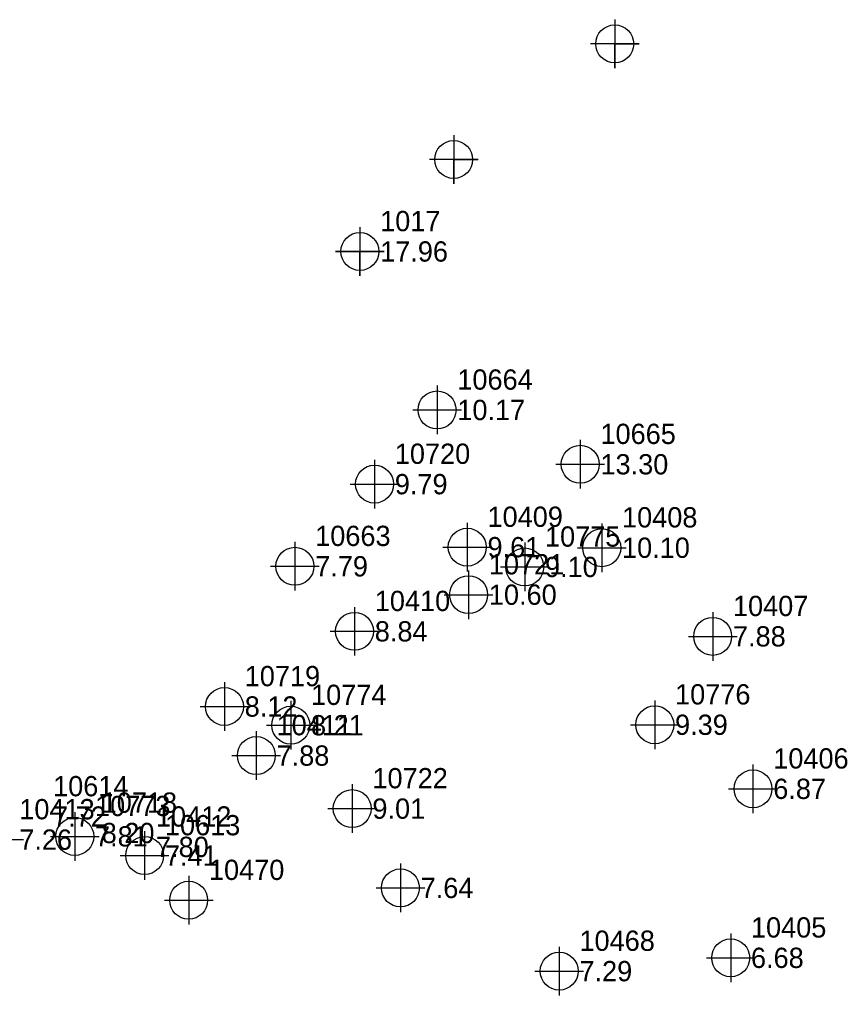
# Model space of a CAD drawing. Extents: x 2062781 to 2066835, y 358981 to 366501.
# Drawn here: x 2065189 to 2065291.1, y 361579.9 to 361700.3 of the extents above; entities that cross this region are included whole.
import ezdxf

# ---------------------------------------------------------------- set-up
doc = ezdxf.new("R2010")
doc.units = 0
for name, color, linetype in [('COGO Default Point Elevation', 7, 'Continuous'), ('COGO Default Point Number', 7, 'Continuous'), ('Exist DTM Breakline Underwater Cogo Elevation', 7, 'Continuous'), ('Exist DTM Breakline Underwater Cogo Number', 7, 'Continuous'), ('Exist DTM Breakline Underwater Cogo Point CELL', 7, 'Continuous'), ('Exist DTM Regular Point CELL', 7, 'Continuous'), ('Exist DTM Regular Point Underwater CELL', 7, 'Continuous')]:
    doc.layers.add(name, color=color, linetype=linetype)

msp = doc.modelspace()

# ---------------------------------------------------------------- linework, layer by layer
at = {"layer": 'Exist DTM Breakline Underwater Cogo Point CELL'}
msp.add_lwpolyline([(2065230.99, 361674.65), (2065230.99, 361668.65), (2065230.99, 361671.65), (2065233.99, 361671.65), (2065227.99, 361671.65)], dxfattribs=at)
msp.add_circle((2065230.99, 361671.65), 2.34, dxfattribs=at)
at = {"layer": 'Exist DTM Regular Point CELL'}
for points in [[(2065262.42, 361700.25), (2065262.42, 361694.25), (2065262.42, 361697.25), (2065265.42, 361697.25), (2065259.42, 361697.25)], [(2065242.56, 361685.99), (2065242.56, 361679.99), (2065242.56, 361682.99), (2065245.56, 361682.99), (2065239.56, 361682.99)]]:
    msp.add_lwpolyline(points, dxfattribs=at)
for centre in [(2065262.42, 361697.25), (2065242.56, 361682.99)]:
    msp.add_circle(centre, 2.34, dxfattribs=at)
at = {"layer": 'Exist DTM Regular Point Underwater CELL'}
for points in [[(2065230.99, 361674.65), (2065230.99, 361671.65)], [(2065227.99, 361671.65), (2065230.99, 361671.65)], [(2065230.99, 361671.65), (2065233.99, 361671.65)], [(2065230.99, 361671.65), (2065230.99, 361668.65)], [(2065240.51, 361655.11), (2065240.51, 361652.11)], [(2065237.51, 361652.11), (2065240.51, 361652.11)], [(2065240.51, 361652.11), (2065243.51, 361652.11)], [(2065240.51, 361652.11), (2065240.51, 361649.11)], [(2065258.16, 361648.41), (2065258.16, 361645.41)], [(2065232.8, 361645.96), (2065232.8, 361642.96)], [(2065255.16, 361645.41), (2065258.16, 361645.41)], [(2065258.16, 361645.41), (2065261.16, 361645.41)], [(2065258.16, 361645.41), (2065258.16, 361642.41)], [(2065229.8, 361642.96), (2065232.8, 361642.96)], [(2065232.8, 361642.96), (2065235.8, 361642.96)], [(2065232.8, 361642.96), (2065232.8, 361639.96)], [(2065244.23, 361638.19), (2065244.23, 361635.19)], [(2065260.82, 361638.12), (2065260.82, 361635.12)], [(2065222.98, 361635.83), (2065222.98, 361632.83)], [(2065251.32, 361635.75), (2065251.32, 361632.75)], [(2065241.23, 361635.19), (2065244.23, 361635.19)], [(2065244.23, 361635.19), (2065247.23, 361635.19)], [(2065244.23, 361635.19), (2065244.23, 361632.19)], [(2065257.82, 361635.12), (2065260.82, 361635.12)], [(2065260.82, 361635.12), (2065263.82, 361635.12)], [(2065260.82, 361635.12), (2065260.82, 361632.12)], [(2065219.98, 361632.83), (2065222.98, 361632.83)], [(2065222.98, 361632.83), (2065225.98, 361632.83)], [(2065222.98, 361632.83), (2065222.98, 361629.83)], [(2065244.4, 361632.33), (2065244.4, 361629.33)], [(2065248.32, 361632.75), (2065251.32, 361632.75)], [(2065251.32, 361632.75), (2065254.32, 361632.75)], [(2065251.32, 361632.75), (2065251.32, 361629.75)], [(2065241.4, 361629.33), (2065244.4, 361629.33)], [(2065244.4, 361629.33), (2065247.4, 361629.33)], [(2065244.4, 361629.33), (2065244.4, 361626.33)], [(2065230.33, 361627.81), (2065230.33, 361624.81)], [(2065274.5, 361627.19), (2065274.5, 361624.19)], [(2065227.33, 361624.81), (2065230.33, 361624.81)], [(2065230.33, 361624.81), (2065233.33, 361624.81)], [(2065230.33, 361624.81), (2065230.33, 361621.81)], [(2065271.5, 361624.19), (2065274.5, 361624.19)], [(2065274.5, 361624.19), (2065277.5, 361624.19)], [(2065274.5, 361624.19), (2065274.5, 361621.19)], [(2065214.29, 361618.54), (2065214.29, 361615.54)], [(2065267.36, 361616.29), (2065267.36, 361613.29)], [(2065211.29, 361615.54), (2065214.29, 361615.54)], [(2065214.29, 361615.54), (2065217.29, 361615.54)], [(2065214.29, 361615.54), (2065214.29, 361612.54)], [(2065222.47, 361616.23), (2065222.47, 361613.23)], [(2065219.47, 361613.23), (2065222.47, 361613.23)], [(2065222.47, 361613.23), (2065225.47, 361613.23)], [(2065222.47, 361613.23), (2065222.47, 361610.23)], [(2065264.36, 361613.29), (2065267.36, 361613.29)], [(2065267.36, 361613.29), (2065270.36, 361613.29)], [(2065267.36, 361613.29), (2065267.36, 361610.29)], [(2065218.22, 361612.49), (2065218.22, 361609.49)], [(2065215.22, 361609.49), (2065218.22, 361609.49)], [(2065218.22, 361609.49), (2065221.22, 361609.49)], [(2065218.22, 361609.49), (2065218.22, 361606.49)], [(2065279.47, 361608.39), (2065279.47, 361605.39)], [(2065230.04, 361605.95), (2065230.04, 361602.95)], [(2065276.47, 361605.39), (2065279.47, 361605.39)], [(2065279.47, 361605.39), (2065282.47, 361605.39)], [(2065279.47, 361605.39), (2065279.47, 361602.39)], [(2065195.83, 361602.52), (2065195.83, 361599.52)], [(2065227.04, 361602.95), (2065230.04, 361602.95)], [(2065230.04, 361602.95), (2065233.04, 361602.95)], [(2065230.04, 361602.95), (2065230.04, 361599.95)], [(2065192.83, 361599.52), (2065195.83, 361599.52)], [(2065195.83, 361599.52), (2065198.83, 361599.52)], [(2065195.83, 361599.52), (2065195.83, 361596.52)], [(2065204.45, 361600.16), (2065204.45, 361597.16)], [(2065186.49, 361599.13), (2065189.49, 361599.13)], [(2065201.45, 361597.16), (2065204.45, 361597.16)], [(2065204.45, 361597.16), (2065207.45, 361597.16)], [(2065204.45, 361597.16), (2065204.45, 361594.16)], [(2065235.99, 361596.17), (2065235.99, 361593.17)], [(2065209.88, 361594.65), (2065209.88, 361591.65)], [(2065232.99, 361593.17), (2065235.99, 361593.17)], [(2065235.99, 361593.17), (2065238.99, 361593.17)], [(2065235.99, 361593.17), (2065235.99, 361590.17)], [(2065206.88, 361591.65), (2065209.88, 361591.65)], [(2065209.88, 361591.65), (2065212.88, 361591.65)], [(2065209.88, 361591.65), (2065209.88, 361588.65)], [(2065276.72, 361587.55), (2065276.72, 361584.55)], [(2065255.57, 361585.91), (2065255.57, 361582.91)], [(2065273.72, 361584.55), (2065276.72, 361584.55)], [(2065276.72, 361584.55), (2065279.72, 361584.55)], [(2065276.72, 361584.55), (2065276.72, 361581.55)], [(2065252.57, 361582.91), (2065255.57, 361582.91)], [(2065255.57, 361582.91), (2065258.57, 361582.91)], [(2065255.57, 361582.91), (2065255.57, 361579.91)]]:
    msp.add_lwpolyline(points, dxfattribs=at)
for centre in [(2065230.99, 361671.65), (2065240.51, 361652.11), (2065258.16, 361645.41), (2065232.8, 361642.96), (2065244.23, 361635.19), (2065260.82, 361635.12), (2065222.98, 361632.83), (2065251.32, 361632.75), (2065244.4, 361629.33), (2065230.33, 361624.81), (2065274.5, 361624.19), (2065214.29, 361615.54), (2065222.47, 361613.23), (2065267.36, 361613.29), (2065218.22, 361609.49), (2065279.47, 361605.39), (2065230.04, 361602.95), (2065195.83, 361599.52), (2065204.45, 361597.16), (2065235.99, 361593.17), (2065209.88, 361591.65), (2065276.72, 361584.55), (2065255.57, 361582.91)]:
    msp.add_circle(centre, 2.34, dxfattribs=at)

# ---------------------------------------------------------------- texts
at = {"layer": 'COGO Default Point Elevation'}
for s, p in [('10.17', (2065243.01, 361650.86)), ('13.30', (2065260.66, 361644.16)), ('9.79', (2065235.3, 361641.71)), ('9.61', (2065246.73, 361633.94)), ('10.10', (2065263.32, 361633.87)), ('7.79', (2065225.48, 361631.58)), ('9.10', (2065253.82, 361631.5)), ('10.60', (2065246.9, 361628.08)), ('8.84', (2065232.83, 361623.56)), ('7.88', (2065277, 361622.94)), ('8.12', (2065216.79, 361614.29)), ('8.21', (2065224.97, 361611.98)), ('9.39', (2065269.86, 361612.04)), ('7.88', (2065220.72, 361608.24)), ('6.87', (2065281.97, 361604.14)), ('9.01', (2065232.54, 361601.7)), ('7.72', (2065193.16, 361600.72)), ('7.81', (2065198.33, 361598.28)), ('8.20', (2065199.15, 361598.69)), ('7.26', (2065188.99, 361597.88)), ('7.80', (2065205.85, 361596.98)), ('7.41', (2065206.95, 361595.91)), ('7.64', (2065238.49, 361591.92)), ('6.68', (2065279.22, 361583.3)), ('7.29', (2065258.07, 361581.66))]:
    msp.add_text(s, height=2.5, dxfattribs=at).set_placement(p)
at = {"layer": 'COGO Default Point Number'}
for s, p in [('10664', (2065243.01, 361654.61)), ('10665', (2065260.66, 361647.91)), ('10720', (2065235.3, 361645.46)), ('10409', (2065246.73, 361637.69)), ('10408', (2065263.32, 361637.62)), ('10663', (2065225.48, 361635.33)), ('10775', (2065253.82, 361635.25)), ('10721', (2065246.9, 361631.83)), ('10410', (2065232.83, 361627.31)), ('10407', (2065277, 361626.69)), ('10719', (2065216.79, 361618.04)), ('10774', (2065224.97, 361615.73)), ('10776', (2065269.86, 361615.79)), ('10411', (2065220.72, 361611.99)), ('10406', (2065281.97, 361607.89)), ('10722', (2065232.54, 361605.45)), ('10614', (2065193.16, 361604.47)), ('10773', (2065198.33, 361602.03)), ('10718', (2065199.15, 361602.44)), ('10413', (2065188.99, 361601.63)), ('10412', (2065205.85, 361600.73)), ('10613', (2065206.95, 361599.66)), ('10470', (2065212.38, 361594.15)), ('10405', (2065279.22, 361587.05)), ('10468', (2065258.07, 361585.41))]:
    msp.add_text(s, height=2.5, dxfattribs=at).set_placement(p)
at = {"layer": 'Exist DTM Breakline Underwater Cogo Elevation'}
msp.add_text('17.96', height=2.5, dxfattribs=at).set_placement((2065233.49, 361670.4))
msp.add_text('17.96', height=2.5, dxfattribs=at).set_placement((2065233.49, 361670.4))
at = {"layer": 'Exist DTM Breakline Underwater Cogo Number'}
msp.add_text('1017', height=2.5, dxfattribs=at).set_placement((2065233.49, 361674.15))
msp.add_text('1017', height=2.5, dxfattribs=at).set_placement((2065233.49, 361674.15))

doc.saveas('drawing.dxf')
